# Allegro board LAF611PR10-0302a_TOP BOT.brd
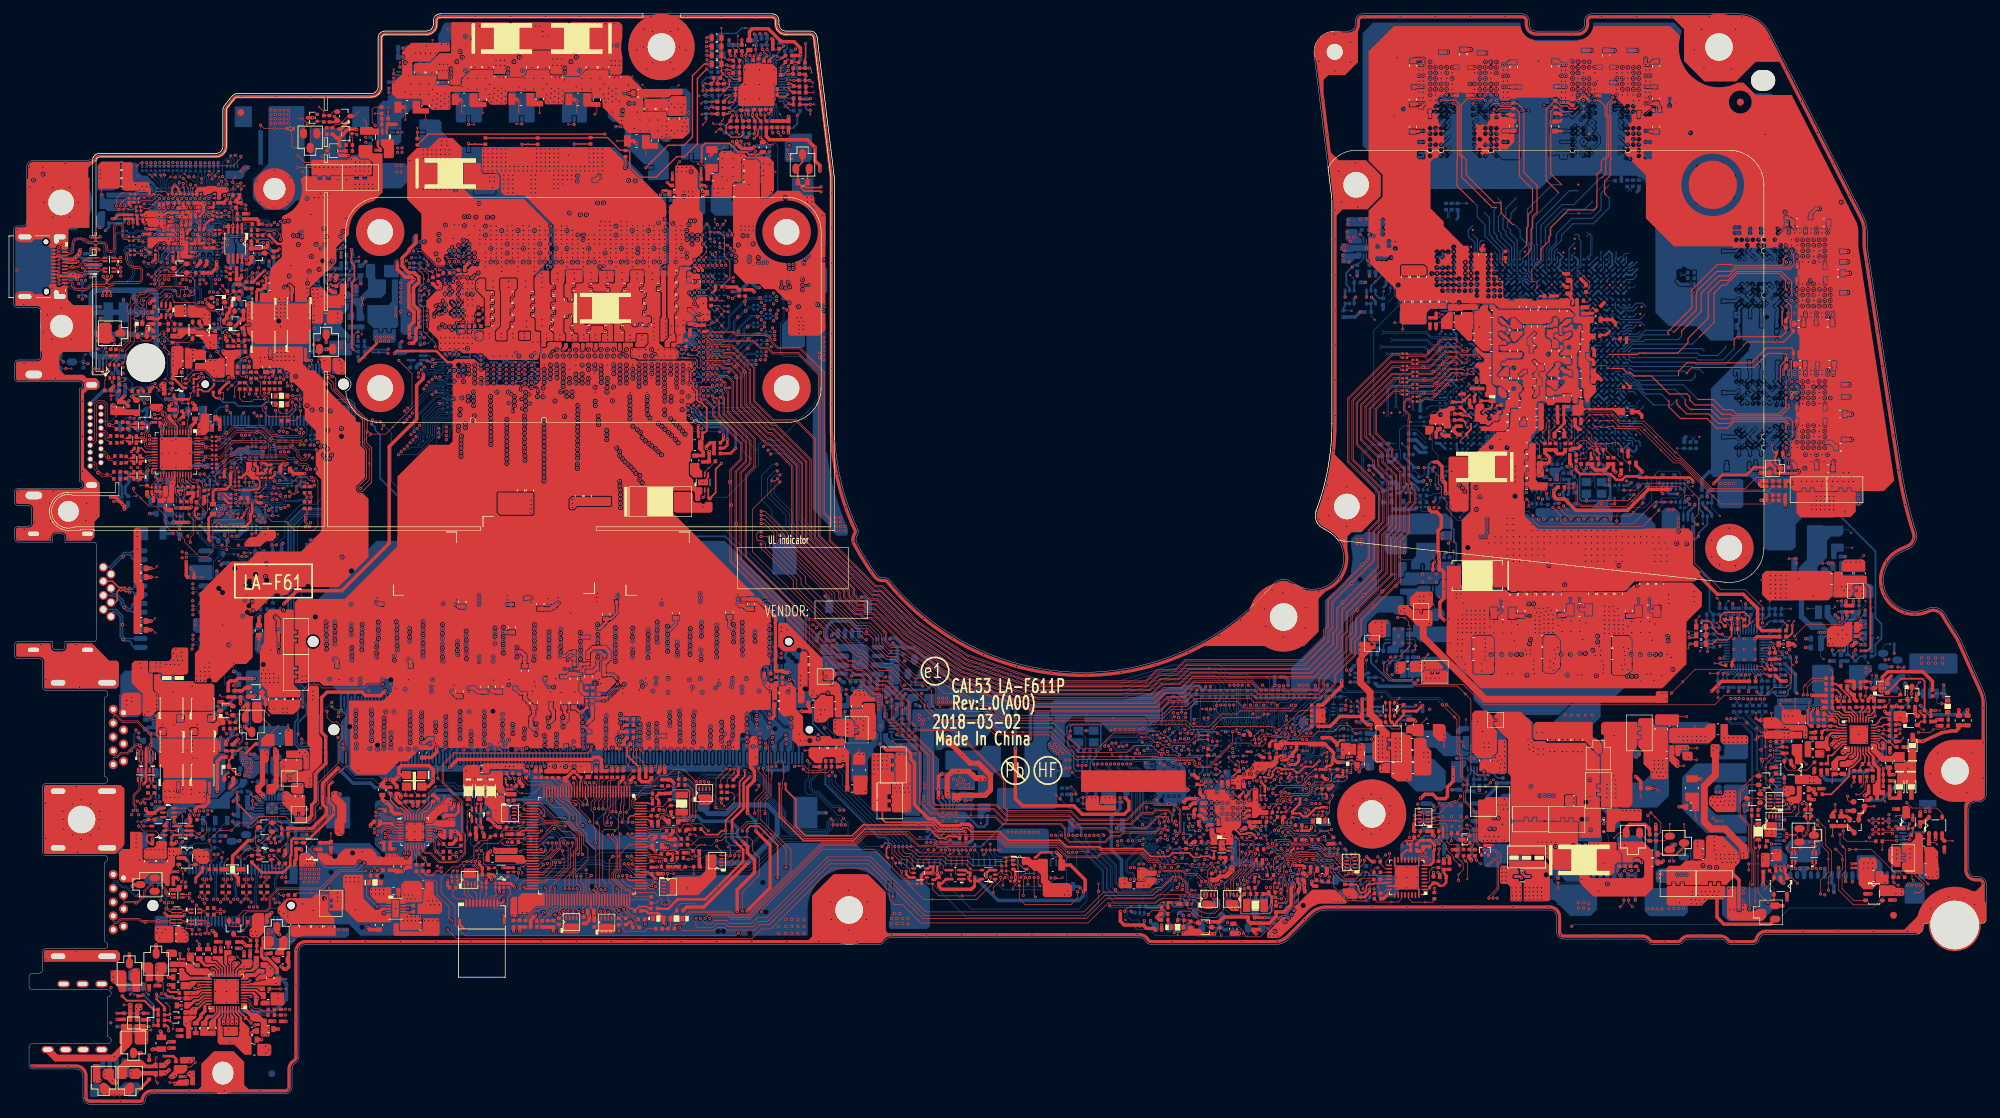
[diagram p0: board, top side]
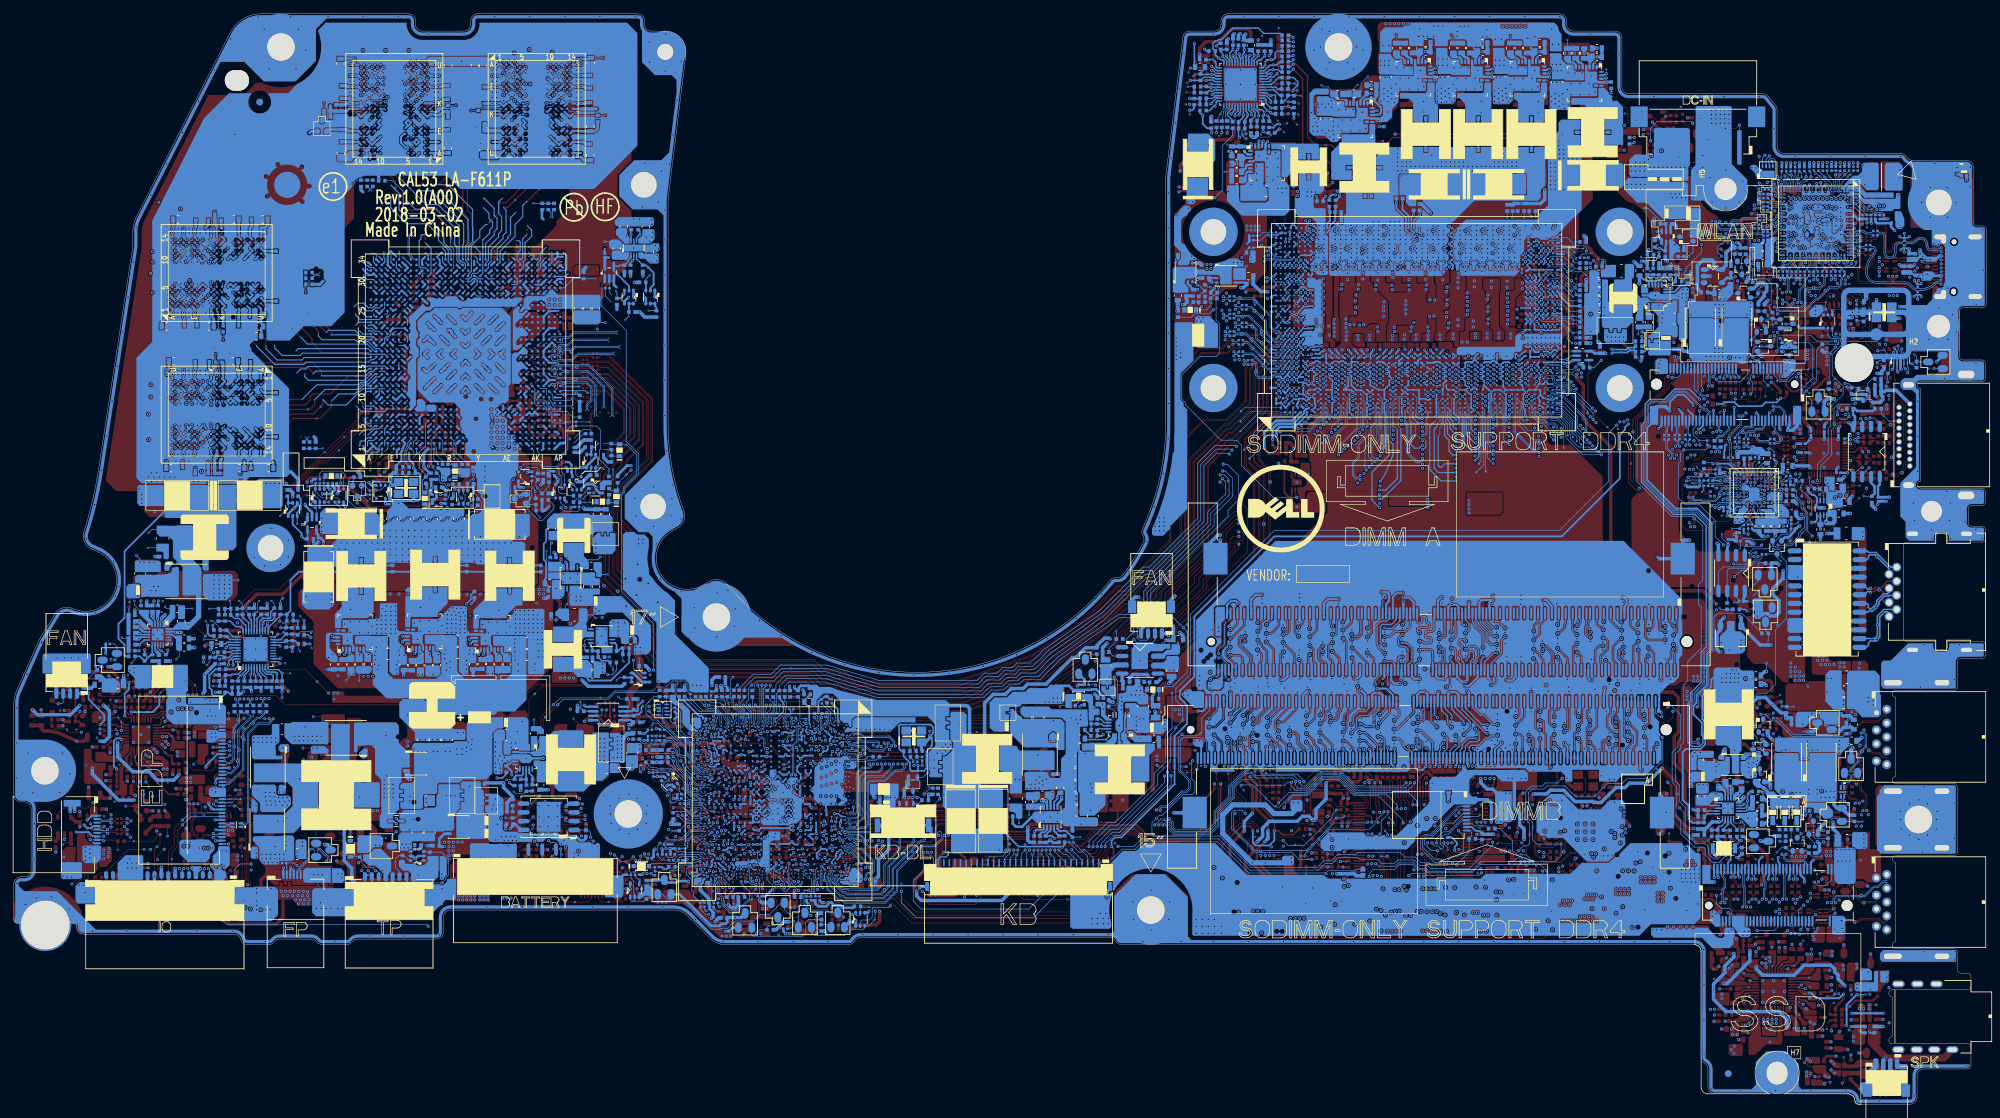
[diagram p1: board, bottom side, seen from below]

Outline 285.35 x 157.8 mm; copper layers: TOP, GND1, IN1, VCC, IN2, IN3, GND2, IN4, GND3, BOTTOM. Coordinates in mm from the lower left corner of the outline.

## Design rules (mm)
net group DDR4_RESET_20: nets DDR_DRAMRST# H_DRAMRST#
net group DDR_A_CLK0: nets DDR_A_CLK0 DDR_A_CLK#0
net group DDR_A_CLK1: nets DDR_A_CLK1 DDR_A_CLK#1
net group DDR_B_CLK0: nets DDR_B_CLK0 DDR_B_CLK#0
net group DDR_B_CLK1: nets DDR_B_CLK1 DDR_B_CLK#1
net group DIFFPAIR0: nets N26540304 N26540350
net group DIFFPAIR1: nets N26540312 N26540344
net group DIFFPAIR2: nets N26540318 N26540338
net group DIFFPAIR3: nets N26540324 N26540332
net group DIFFPAIR4: nets FB_A_CLK1 FB_A_CLK1#
net group DIFFPAIR5: nets FB_A_WCK3 FB_A_WCK#3
net group DIFFPAIR6: nets FB_A_WCK1 FB_A_WCK#1
net group DIFFPAIR7: nets FB_A_CLK0 FB_A_CLK0#
net group DIFFPAIR8: nets FB_B_CLK1 FB_B_CLK1#
net group DIFFPAIR9: nets FB_B_WCK2 FB_B_WCK#2
net group DIFFPAIR10: nets FB_B_WCK1 FB_B_WCK#1
net group DIFFPAIR11: nets FB_B_CLK0 FB_B_CLK0#
net group DIFFPAIR12: nets FB_A_WCK2 FB_A_WCK#2
net group DIFFPAIR13: nets FB_B_WCK3 FB_B_WCK#3
net group DIFFPAIR14: nets FB_B_WCK0 FB_B_WCK#0
net group DIFFPAIR15: nets FB_A_WCK0 FB_A_WCK#0
net group DIFFPAIR16: nets PCH_SMBCLK PCH_SMBDATA
net group DIFFPAIR17: nets CPU_DP1_N1_C CPU_DP1_P1_C
net group DIFFPAIR18: nets CPU_DP1_N0_C CPU_DP1_P0_C
net group DIFFPAIR19: nets CPU_DP1_N2_C CPU_DP1_P2_C
net group DIFFPAIR20: nets CPU_DP1_N3_C CPU_DP1_P3_C
net group DIFFPAIR21: nets PCIE_PTX_C_CRX_N23 PCIE_PTX_C_DRX_P23
net group DIFFPAIR22: nets TBT_A_SBU1 TBT_A_SBU2
net group PCIE_PRX_C_DTX_21: nets PCIE_PRX_C_DTX_N21 PCIE_PRX_C_DTX_P21
net group PCIE_PRX_C_DTX_22: nets PCIE_PRX_C_DTX_N22 PCIE_PRX_C_DTX_P22
net group PCIE_PRX_C_DTX_23: nets PCIE_PRX_C_DTX_N23 PCIE_PRX_C_DTX_P23
net group PCIE_PRX_C_DTX_24: nets PCIE_PRX_C_DTX_N24 PCIE_PRX_C_DTX_P24
net group PCIE_PRX_DTX_21: nets PCIE_PRX_DTX_N21 PCIE_PRX_DTX_P21
net group PCIE_PRX_DTX_22: nets PCIE_PRX_DTX_N22 PCIE_PRX_DTX_P22
net group PCIE_PRX_DTX_23: nets PCIE_PRX_DTX_N23 PCIE_PRX_DTX_P23
net group PCIE_PRX_DTX_24: nets PCIE_PRX_DTX_N24 PCIE_PRX_DTX_P24
net group PCIE_PTX_C_DRX_21: nets PCIE_PTX_C_DRX_N21 PCIE_PTX_C_DRX_P21
net group PCIE_PTX_C_DRX_22: nets PCIE_PTX_C_DRX_N22 PCIE_PTX_C_DRX_P22
net group PCIE_PTX_C_DRX_24: nets PCIE_PTX_C_DRX_N24 PCIE_PTX_C_DRX_P24
net group PCIE_PTX_DRX_21: nets PCIE_PTX_DRX_N21 PCIE_PTX_DRX_P21
net group PCIE_PTX_DRX_22: nets PCIE_PTX_DRX_N22 PCIE_PTX_DRX_P22
net group PCIE_PTX_DRX_23: nets PCIE_PTX_DRX_N23 PCIE_PTX_DRX_P23
net group PCIE_PTX_DRX_24: nets PCIE_PTX_DRX_N24 PCIE_PTX_DRX_P24
net group PCIE_RCOMP: nets PCIE_RCOMPN PCIE_RCOMPP
net group TBTA_DIG_AUD_: nets TBTA_DIG_AUD_N TBTA_DIG_AUD_P
net group THERMAL_10: nets NCT7718_DXN NCT7718_DXP
net group USB20_5_R: nets USB20_N5_R USB20_P5_R
net group USB20_8_R: nets USB20_N8_R USB20_P8_R
net group USB20_11: nets USB20_N11 USB20_P11
net group AR_TO_TYPEC_15: nets TBT_A_AUX_N TBT_A_AUX_N_C TBT_A_AUX_P TBT_A_AUX_P_C
net group ASYN_SIGNALS_12: nets ALL_SYS_PWRGD CATERR# DGPU_HOLD_RST# DGPU_PEX_RST# DGPU_PEX_RST#_R H_CPUPWRGD H_PLTRST_CPU# H_PROCHOT# H_PROCHOT#_R H_THERMTRIP# H_THERMTRIP#_C H_THERMTRIP#_R H_VCCST_PWRGD N17462343 PCH_PLTRST# PLTRST# PROCHOT RUNPWROK TBT_RST#_R VCCST_PWRGD_CPU XDP_BPM#0 XDP_BPM#1 XDP_BPM#2 XDP_BPM#3
net group ASYN_SIGNALS_OTHER_15/12: nets CPU_TRIGOUT CPU_TRIGOUT_R H_PM_DOWN H_PM_DOWN_R H_PM_SYNC_PCH H_PM_SYNC_R PCH_TRIGOUT PCH_TRIGOUT_R
net group ASYN_SIGNALS_PECI_18/12: nets H_PECI PECI_EC PECI_EC_R
net group ASYN_SIGNALS_SVID_15/12: nets VR_SVID_ALERT# VR_SVID_ALERT#_R VR_SVID_CLK VR_SVID_DATA
net group AUDIO_12: nets CBN CBP CPVEE
net group AUDIO_ANALOG_PORT_10: nets +MIC2-VREFO AUD_HP1_JACK_L AUD_HP1_JACK_L1 AUD_HP1_JACK_R AUD_HP1_JACK_R1 HPOUT_L HPOUT_R LINE1-L_C LINE1-L_R LINE1_L LINE1_R
net group AUDIO_LDO: nets LDO1_CAP LDO2_CAP LDO3_CAP
net group AUDIO_SPEAKER_10: nets AUD_SPK_L+ AUD_SPK_L+_C AUD_SPK_L- AUD_SPK_L-_C AUD_SPK_R+ AUD_SPK_R+_C AUD_SPK_R- AUD_SPK_R-_C RING2 RING2_R SLEEVE SLEEVE_R
net group CLK_DIFF: nets CLK_PCIE_N0 CLK_PCIE_N7 CLK_PCIE_N9 CLK_PCIE_N14 CLK_PCIE_N15 CLK_PCIE_P0 CLK_PCIE_P7 CLK_PCIE_P9 CLK_PCIE_P14 CLK_PCIE_P15 CPU_24MHZ_N CPU_24MHZ_P PCH_CPU_BCLK_N PCH_CPU_BCLK_P PCH_CPU_PCIBCLK_N PCH_CPU_PCIBCLK_P PCH_XDP_CLK_N PCH_XDP_CLK_P
net group CLK_SRCCLKREQ: nets CLKREQ_PCIE#0 CLKREQ_PCIE#0_R CLKREQ_PCIE#7 CLKREQ_PCIE#9 CLKREQ_PCIE#14 CLKREQ_PCIE#14_R CLKREQ_PCIE#15 CLKREQ_PCIE#15_R PEX_CLKREQ#
net group CLKIN_XTAL: nets CLKREQ_CNV# REFCLK_CNV REFCLK_CNV_H
net group CNVI: nets CLK_CNV_PRX_DTX_N CLK_CNV_PRX_DTX_P CLK_CNV_PRX_R_DTX_N CLK_CNV_PRX_R_DTX_P CLK_CNV_PTX_DRX_N CLK_CNV_PTX_DRX_P CLK_CNV_PTX_R_DRX_N CLK_CNV_PTX_R_DRX_P CNV_PRX_DTX_N0 CNV_PRX_DTX_N1 CNV_PRX_DTX_P0 CNV_PRX_DTX_P1 CNV_PRX_R_DTX_N0 CNV_PRX_R_DTX_N1 CNV_PRX_R_DTX_P0 CNV_PRX_R_DTX_P1 CNV_PTX_DRX_N0 CNV_PTX_DRX_N1 CNV_PTX_DRX_P0 CNV_PTX_DRX_P1 CNV_PTX_R_DRX_N0 CNV_PTX_R_DRX_N1 CNV_PTX_R_DRX_P0 CNV_PTX_R_DRX_P1
net group CNVI_BRI_RGI: nets CNV_BRI_PRX_DTX CNV_BRI_PTX_DRX CNV_RGI_PRX_DTX CNV_RGI_PTX_DRX
net group CPU_PEG_RCOMP_15: nets PEG_RCOMP
net group CRITICAL_ RESET_MANAGEMENT_15: nets 1.2V_VDDQ_EN AC_PRESENT CNV_RF_RESET# HW_ACAV_IN LAN_WAKE# LANWAKE# ME_SUS_PWR_ACK PCH_BATLOW# PCH_DPWROK PCH_PCIE_WAKE# PCH_PWROK PCH_RSMRST# PCH_RSMRST#_R PCIE_WAKE# RESET_N RTM_RST# SIO_PWRBTN# SIO_SLP_S0# SIO_SLP_S0#_PCH SIO_SLP_S3# SIO_SLP_S3#_AR SIO_SLP_S3#_PCH SIO_SLP_S4# SIO_SLP_S4#_PCH SYS_PWROK SYS_RESET# TBT_PCIE_WAKE_N TBT_RESET_N TBT_RESET_N_EC# TBTA_MRESET USB_EN# VCCIO_EN VR_ON
net group DDR4_COMP: nets SM_RCOMP0 SM_RCOMP1 SM_RCOMP2
net group DDRA_CMD: nets DDR_A_ACT# DDR_A_ALERT# DDR_A_BA0 DDR_A_BA1 DDR_A_BG0 DDR_A_BG1 DDR_A_MA0 DDR_A_MA1 DDR_A_MA2 DDR_A_MA3 DDR_A_MA4 DDR_A_MA5 DDR_A_MA6 DDR_A_MA7 DDR_A_MA8 DDR_A_MA9 DDR_A_MA10 DDR_A_MA11 DDR_A_MA12 DDR_A_MA13 DDR_A_MA14_WE# DDR_A_MA15_CAS# DDR_A_MA16_RAS# DDR_A_PAR
net group DDRA_CTRL: nets DDR_A_CKE0 DDR_A_CKE1 DDR_A_CS#0 DDR_A_CS#1 DDR_A_ODT0 DDR_A_ODT1
net group DDRA_D0: nets DDR_A_D0 DDR_A_D1 DDR_A_D2 DDR_A_D3 DDR_A_D4 DDR_A_D5 DDR_A_D6 DDR_A_D7
net group DDRA_D1: nets DDR_A_D8 DDR_A_D9 DDR_A_D10 DDR_A_D11 DDR_A_D12 DDR_A_D13 DDR_A_D14 DDR_A_D15
net group DDRA_D2: nets DDR_A_D16 DDR_A_D17 DDR_A_D18 DDR_A_D19 DDR_A_D20 DDR_A_D21 DDR_A_D22 DDR_A_D23
net group DDRA_D3: nets DDR_A_D24 DDR_A_D25 DDR_A_D26 DDR_A_D27 DDR_A_D28 DDR_A_D29 DDR_A_D30 DDR_A_D31
net group DDRA_D4: nets DDR_A_D32 DDR_A_D33 DDR_A_D34 DDR_A_D35 DDR_A_D36 DDR_A_D37 DDR_A_D38 DDR_A_D39
net group DDRA_D5: nets DDR_A_D40 DDR_A_D41 DDR_A_D42 DDR_A_D43 DDR_A_D44 DDR_A_D45 DDR_A_D46 DDR_A_D47
net group DDRA_D6: nets DDR_A_D48 DDR_A_D49 DDR_A_D50 DDR_A_D51 DDR_A_D52 DDR_A_D53 DDR_A_D54 DDR_A_D55
net group DDRA_D7: nets DDR_A_D56 DDR_A_D57 DDR_A_D58 DDR_A_D59 DDR_A_D60 DDR_A_D61 DDR_A_D62 DDR_A_D63
net group DDRA_DQS_25: nets DDR_A_DQS0 DDR_A_DQS1 DDR_A_DQS2 DDR_A_DQS3 DDR_A_DQS4 DDR_A_DQS5 DDR_A_DQS6 DDR_A_DQS7 DDR_A_DQS#0 DDR_A_DQS#1 DDR_A_DQS#2 DDR_A_DQS#3 DDR_A_DQS#4 DDR_A_DQS#5 DDR_A_DQS#6 DDR_A_DQS#7
net group DDRB_CMD: nets DDR_B_ACT# DDR_B_ALERT# DDR_B_BA0 DDR_B_BA1 DDR_B_BG0 DDR_B_BG1 DDR_B_MA0 DDR_B_MA1 DDR_B_MA2 DDR_B_MA3 DDR_B_MA4 DDR_B_MA5 DDR_B_MA6 DDR_B_MA7 DDR_B_MA8 DDR_B_MA9 DDR_B_MA10 DDR_B_MA11 DDR_B_MA12 DDR_B_MA13 DDR_B_MA14_WE# DDR_B_MA15_CAS# DDR_B_MA16_RAS# DDR_B_PAR
net group DDRB_CTRL: nets DDR_B_CKE0 DDR_B_CKE1 DDR_B_CS#0 DDR_B_CS#1 DDR_B_ODT0 DDR_B_ODT1
net group DDRB_D0: nets DDR_B_D0 DDR_B_D1 DDR_B_D2 DDR_B_D3 DDR_B_D4 DDR_B_D5 DDR_B_D6 DDR_B_D7
net group DDRB_D1: nets DDR_B_D8 DDR_B_D9 DDR_B_D10 DDR_B_D11 DDR_B_D12 DDR_B_D13 DDR_B_D14 DDR_B_D15
net group DDRB_D2: nets DDR_B_D16 DDR_B_D17 DDR_B_D18 DDR_B_D19 DDR_B_D20 DDR_B_D21 DDR_B_D22 DDR_B_D23
net group DDRB_D3: nets DDR_B_D24 DDR_B_D25 DDR_B_D26 DDR_B_D27 DDR_B_D28 DDR_B_D29 DDR_B_D30 DDR_B_D31
net group DDRB_D4: nets DDR_B_D32 DDR_B_D33 DDR_B_D34 DDR_B_D35 DDR_B_D36 DDR_B_D37 DDR_B_D38 DDR_B_D39
net group DDRB_D5: nets DDR_B_D40 DDR_B_D41 DDR_B_D42 DDR_B_D43 DDR_B_D44 DDR_B_D45 DDR_B_D46 DDR_B_D47
net group DDRB_D6: nets DDR_B_D48 DDR_B_D49 DDR_B_D50 DDR_B_D51 DDR_B_D52 DDR_B_D53 DDR_B_D54 DDR_B_D55
net group DDRB_D7: nets DDR_B_D56 DDR_B_D57 DDR_B_D58 DDR_B_D59 DDR_B_D60 DDR_B_D61 DDR_B_D62 DDR_B_D63
net group DDRB_DQS_25: nets DDR_B_DQS0 DDR_B_DQS1 DDR_B_DQS2 DDR_B_DQS3 DDR_B_DQS4 DDR_B_DQS5 DDR_B_DQS6 DDR_B_DQS7 DDR_B_DQS#0 DDR_B_DQS#1 DDR_B_DQS#2 DDR_B_DQS#3 DDR_B_DQS#4 DDR_B_DQS#5 DDR_B_DQS#6 DDR_B_DQS#7
net group DMI: nets DMI_CRX_PTX_N0 DMI_CRX_PTX_N1 DMI_CRX_PTX_N2 DMI_CRX_PTX_N3 DMI_CRX_PTX_P0 DMI_CRX_PTX_P1 DMI_CRX_PTX_P2 DMI_CRX_PTX_P3 DMI_CTX_PRX_N0 DMI_CTX_PRX_N1 DMI_CTX_PRX_N2 DMI_CTX_PRX_N3 DMI_CTX_PRX_P0 DMI_CTX_PRX_P1 DMI_CTX_PRX_P2 DMI_CTX_PRX_P3
net group DP_MAIN_15: nets CPU_DP1_AUXN CPU_DP1_AUXN_C CPU_DP1_AUXP CPU_DP1_AUXP_C CPU_DP1_N0 CPU_DP1_N1 CPU_DP1_N2 CPU_DP1_N3 CPU_DP1_P0 CPU_DP1_P1 CPU_DP1_P2 CPU_DP1_P3
net group EDP: nets EDP_AUXN EDP_AUXN_C EDP_AUXP EDP_AUXP_C EDP_TXN0 EDP_TXN0_C EDP_TXN1 EDP_TXN1_C EDP_TXP0 EDP_TXP0_C EDP_TXP1 EDP_TXP1_C
net group EDP_COMP_20: nets DP_RCOMP
net group ESPI_15: nets ESPI_CLK ESPI_CLK_R ESPI_CS# ESPI_IO0 ESPI_IO0_R ESPI_IO1 ESPI_IO1_R ESPI_IO2 ESPI_IO2_R ESPI_IO3 ESPI_IO3_R
net group HDA_15: nets CPU_DISPA_BCLK CPU_DISPA_BCLK_R CPU_DISPA_SDI CPU_DISPA_SDI_C CPU_DISPA_SDO CPU_DISPA_SDO_R DMIC_CLK DMIC_CLK_EDP DMIC_DATA DMIC_DATA_EDP HDA_CODEC_SDIN0 PCH_AZ_BITCLK PCH_AZ_CODEC_BITCLK PCH_AZ_CODEC_SDIN0 PCH_AZ_CODEC_SDOUT PCH_AZ_CODEC_SYNC PCH_AZ_SDOUT PCH_AZ_SYNC
net group HDMI: nets HDMI_CLKN HDMI_CLKP HDMI_L_CLKN HDMI_L_CLKP HDMI_L_TX_N0 HDMI_L_TX_N1 HDMI_L_TX_N2 HDMI_L_TX_P0 HDMI_L_TX_P1 HDMI_L_TX_P2 HDMI_TX_N0 HDMI_TX_N1 HDMI_TX_N2 HDMI_TX_P0 HDMI_TX_P1 HDMI_TX_P2 IFPC_CLK_CN IFPC_CLK_CP IFPC_CLK_N IFPC_CLK_P IFPC_TX0_CN IFPC_TX0_CP IFPC_TX0_N IFPC_TX0_P IFPC_TX1_CN IFPC_TX1_CP IFPC_TX1_N IFPC_TX1_P IFPC_TX2_CN IFPC_TX2_CP IFPC_TX2_N IFPC_TX2_P
net group HDMI_DDC_15: nets HDMI_CTRL_CLK HDMI_CTRL_DAT IFPC_I2C_8409_CLK IFPC_I2C_8409_DAT IFPC_I2C_CLK IFPC_I2C_CLK_R IFPC_I2C_DAT IFPC_I2C_DAT_R
net group I2C_15: nets CLK_TP_SIO DAT_TP_SIO I2C_SCL_TP I2C_SDA_TP
net group LAN_30: nets LAN_MDIN0 LAN_MDIN1 LAN_MDIN2 LAN_MDIN3 LAN_MDIP0 LAN_MDIP1 LAN_MDIP2 LAN_MDIP3 RJ45_MDIN0 RJ45_MDIN1 RJ45_MDIN2 RJ45_MDIN3 RJ45_MDIP0 RJ45_MDIP1 RJ45_MDIP2 RJ45_MDIP3
net group NVME_PCIE_12: nets PCIE_PRX_DTX_N9 PCIE_PRX_DTX_N10 PCIE_PRX_DTX_N11 PCIE_PRX_DTX_N12 PCIE_PRX_DTX_P9 PCIE_PRX_DTX_P10 PCIE_PRX_DTX_P11 PCIE_PRX_DTX_P12 PCIE_PTX_C_DRX_N9 PCIE_PTX_C_DRX_N10 PCIE_PTX_C_DRX_N11 PCIE_PTX_C_DRX_N12 PCIE_PTX_C_DRX_P9 PCIE_PTX_C_DRX_P10 PCIE_PTX_C_DRX_P11 PCIE_PTX_C_DRX_P12 PCIE_PTX_DRX_N9 PCIE_PTX_DRX_N10 PCIE_PTX_DRX_N11 PCIE_PTX_DRX_N12 PCIE_PTX_DRX_P9 PCIE_PTX_DRX_P10 PCIE_PTX_DRX_P11 PCIE_PTX_DRX_P12
net group PCIE_12: nets PCIE_PRX_C_DTX_N14 PCIE_PRX_C_DTX_P14 PCIE_PRX_DTX_N14 PCIE_PRX_DTX_N15 PCIE_PRX_DTX_P14 PCIE_PRX_DTX_P15 PCIE_PTX_C_DRX_N14 PCIE_PTX_C_DRX_N15 PCIE_PTX_C_DRX_P14 PCIE_PTX_C_DRX_P15 PCIE_PTX_DRX_N14 PCIE_PTX_DRX_N15 PCIE_PTX_DRX_P14 PCIE_PTX_DRX_P15
net group PEG: nets PEG_CRX_C_GTX_N0 PEG_CRX_C_GTX_N1 PEG_CRX_C_GTX_N2 PEG_CRX_C_GTX_N3 PEG_CRX_C_GTX_N4 PEG_CRX_C_GTX_N5 PEG_CRX_C_GTX_N6 PEG_CRX_C_GTX_N7 PEG_CRX_C_GTX_P0 PEG_CRX_C_GTX_P1 PEG_CRX_C_GTX_P2 PEG_CRX_C_GTX_P3 PEG_CRX_C_GTX_P4 PEG_CRX_C_GTX_P5 PEG_CRX_C_GTX_P6 PEG_CRX_C_GTX_P7 PEG_CRX_GTX_N0 PEG_CRX_GTX_N1 PEG_CRX_GTX_N2 PEG_CRX_GTX_N3 PEG_CRX_GTX_N4 PEG_CRX_GTX_N5 PEG_CRX_GTX_N6 PEG_CRX_GTX_N7 PEG_CRX_GTX_P0 PEG_CRX_GTX_P1 PEG_CRX_GTX_P2 PEG_CRX_GTX_P3 PEG_CRX_GTX_P4 PEG_CRX_GTX_P5 PEG_CRX_GTX_P6 PEG_CRX_GTX_P7 PEG_CTX_GRX_N0 PEG_CTX_GRX_N1 PEG_CTX_GRX_N2 PEG_CTX_GRX_N3 PEG_CTX_GRX_N4 PEG_CTX_GRX_N5 PEG_CTX_GRX_N6 PEG_CTX_GRX_N7 PEG_CTX_GRX_P0 PEG_CTX_GRX_P1 PEG_CTX_GRX_P2 PEG_CTX_GRX_P3 PEG_CTX_GRX_P4 PEG_CTX_GRX_P5 PEG_CTX_GRX_P6 PEG_CTX_GRX_P7
net group PEG_1: nets PEG_CTX_C_GRX_N0 PEG_CTX_C_GRX_N1 PEG_CTX_C_GRX_N2 PEG_CTX_C_GRX_N3 PEG_CTX_C_GRX_N4 PEG_CTX_C_GRX_N5 PEG_CTX_C_GRX_N6 PEG_CTX_C_GRX_N7 PEG_CTX_C_GRX_P0 PEG_CTX_C_GRX_P1 PEG_CTX_C_GRX_P2 PEG_CTX_C_GRX_P3 PEG_CTX_C_GRX_P4 PEG_CTX_C_GRX_P5 PEG_CTX_C_GRX_P6 PEG_CTX_C_GRX_P7
net group RTC_15: nets MEC_XTAL1 MEC_XTAL1_R MEC_XTAL2 PCH_RTCRST# PCH_RTCX1 PCH_RTCX2 PCH_SRTCRST# SUSCLK SUSCLK_EC SUSCLK_WLAN
net group SATA_HDD_12: nets SATA3_PRX_C_DTX_N0 SATA3_PRX_C_DTX_P0 SATA3_PRX_DTX_N0 SATA3_PRX_DTX_P0 SATA3_PTX_C_DRX_N0 SATA3_PTX_C_DRX_P0 SATA3_PTX_DRX_N0 SATA3_PTX_DRX_P0
net group SENSE_25: nets FBVDDQ_SENSE N26985058 N26985064 USB2_VBUSSENSE VCC_SA_SENSE VCC_SENSE VCCGT_SENSE VCCIO_SENSE VSS_SA_SENSE VSS_SENSE VSSGT_SENSE VSSIO_SENSE
net group SMBUS_15: nets CLK_SMB DAT_SMB GPU_THM_SMBCLK GPU_THM_SMBDAT PBAT_CHG_SMBCLK PBAT_CHG_SMBDAT PD_I2C_SCL_R PD_I2C_SDA_R SMBCLK SMBDATA SML0_SMBCLK SML0_SMBDATA THM_SML1_CLK THM_SML1_DATA TYPEC_SMBCLK TYPEC_SMBDA VGA_SMB_CK2 VGA_SMB_DA2
net group SPI_15: nets PCH_SPI_CLK PCH_SPI_CLK_R PCH_SPI_CLK_TPM PCH_SPI_CS2# PCH_SPI_CS# PCH_SPI_HOLD# PCH_SPI_HOLD#_R PCH_SPI_SI PCH_SPI_SI_R PCH_SPI_SI_TPM PCH_SPI_SO PCH_SPI_SO_R PCH_SPI_SO_TPM PCH_SPI_WP# PCH_SPI_WP#_R
net group TBT: nets TBT_A_TRX_DTX_N0 TBT_A_TRX_DTX_N0_R TBT_A_TRX_DTX_N1 TBT_A_TRX_DTX_N1_R TBT_A_TRX_DTX_P0 TBT_A_TRX_DTX_P0_R TBT_A_TRX_DTX_P1 TBT_A_TRX_DTX_P1_R TBT_A_TTX_C_DRX_N0 TBT_A_TTX_C_DRX_N1 TBT_A_TTX_C_DRX_P0 TBT_A_TTX_C_DRX_P1 TBT_A_TTX_DRX_N0 TBT_A_TTX_DRX_N1 TBT_A_TTX_DRX_P0 TBT_A_TTX_DRX_P1
net group USB2.0_RBIAS_15: nets USB2_COMP
net group USB2.0_TBT_12: nets TBT_A_USB20_L_NB TBT_A_USB20_L_NT TBT_A_USB20_L_PB TBT_A_USB20_L_PT TBT_A_USB20_N TBT_A_USB20_NB TBT_A_USB20_NT TBT_A_USB20_P TBT_A_USB20_PB TBT_A_USB20_PT
net group USB_2.0_12: nets USB20_N1 USB20_N1_R USB20_N2 USB20_N2_R USB20_N3 USB20_N3_R USB20_N4 USB20_N4_R USB20_N5 USB20_N6 USB20_N6_R USB20_N7 USB20_N8 USB20_N9 USB20_N14 USB20_P1 USB20_P1_R USB20_P2 USB20_P2_R USB20_P3 USB20_P3_R USB20_P4 USB20_P4_R USB20_P5 USB20_P6 USB20_P6_R USB20_P7 USB20_P8 USB20_P9 USB20_P14
net group USB_3.0_12: nets USB3_PRX_DTX_N1 USB3_PRX_DTX_N3 USB3_PRX_DTX_P1 USB3_PRX_DTX_P3 USB3_PRX_L_DTX_N1 USB3_PRX_L_DTX_N3 USB3_PRX_L_DTX_P1 USB3_PRX_L_DTX_P3 USB3_PTX_C_DRX_N1 USB3_PTX_C_DRX_N3 USB3_PTX_C_DRX_P1 USB3_PTX_C_DRX_P3 USB3_PTX_DRX_N1 USB3_PTX_DRX_N3 USB3_PTX_DRX_P1 USB3_PTX_DRX_P3 USB3_PTX_L_DRX_N1 USB3_PTX_L_DRX_N3 USB3_PTX_L_DRX_P1 USB3_PTX_L_DRX_P3
net group VRAM_FB_A_0_12: nets FB_A_D0 FB_A_D1 FB_A_D2 FB_A_D3 FB_A_D4 FB_A_D5 FB_A_D6 FB_A_D7
net group VRAM_FB_A_1_12: nets FB_A_D8 FB_A_D9 FB_A_D10 FB_A_D11 FB_A_D12 FB_A_D13 FB_A_D14 FB_A_D15
net group VRAM_FB_A_2_12: nets FB_A_D16 FB_A_D17 FB_A_D18 FB_A_D19 FB_A_D20 FB_A_D21 FB_A_D22 FB_A_D23
net group VRAM_FB_A_3_12: nets FB_A_D24 FB_A_D25 FB_A_D26 FB_A_D27 FB_A_D28 FB_A_D29 FB_A_D30 FB_A_D31
net group VRAM_FB_A_4_12: nets FB_A_D32 FB_A_D33 FB_A_D34 FB_A_D35 FB_A_D36 FB_A_D37 FB_A_D38 FB_A_D39
net group VRAM_FB_A_5_12: nets FB_A_D40 FB_A_D41 FB_A_D42 FB_A_D43 FB_A_D44 FB_A_D45 FB_A_D46 FB_A_D47
net group VRAM_FB_A_6_12: nets FB_A_D48 FB_A_D49 FB_A_D50 FB_A_D51 FB_A_D52 FB_A_D53 FB_A_D54 FB_A_D55
net group VRAM_FB_A_7_12: nets FB_A_D57 FB_A_D58 FB_A_D59 FB_A_D60 FB_A_D61 FB_A_D62 FB_A_D63
net group VRAM_FB_A_CMD_19/12: nets FB_A_CMD0 FB_A_CMD1 FB_A_CMD2 FB_A_CMD3 FB_A_CMD4 FB_A_CMD5 FB_A_CMD6 FB_A_CMD7 FB_A_CMD8 FB_A_CMD9 FB_A_CMD10 FB_A_CMD11 FB_A_CMD12 FB_A_CMD13 FB_A_CMD14 FB_A_CMD15 FB_A_CMD16 FB_A_CMD17 FB_A_CMD18 FB_A_CMD19 FB_A_CMD20 FB_A_CMD21 FB_A_CMD22 FB_A_CMD23 FB_A_CMD24 FB_A_CMD25 FB_A_CMD26 FB_A_CMD27 FB_A_CMD28 FB_A_CMD29 FB_A_CMD30 FB_A_CMD31
net group VRAM_FB_A_DBI_12: nets FB_A_DBI0 FB_A_DBI1 FB_A_DBI2 FB_A_DBI3 FB_A_DBI4 FB_A_DBI5 FB_A_DBI6 FB_A_DBI7
net group VRAM_FB_A_EDC_12: nets FB_A_EDC0 FB_A_EDC1 FB_A_EDC2 FB_A_EDC3 FB_A_EDC4 FB_A_EDC5 FB_A_EDC6 FB_A_EDC7
net group VRAM_FB_B_0_12: nets FB_B_D0 FB_B_D1 FB_B_D2 FB_B_D3 FB_B_D4 FB_B_D5 FB_B_D6 FB_B_D7
net group VRAM_FB_B_1_12: nets FB_B_D8 FB_B_D9 FB_B_D10 FB_B_D11 FB_B_D12 FB_B_D13 FB_B_D14 FB_B_D15
net group VRAM_FB_B_2_12: nets FB_B_D16 FB_B_D17 FB_B_D18 FB_B_D19 FB_B_D20 FB_B_D21 FB_B_D22 FB_B_D23
net group VRAM_FB_B_3_12: nets FB_B_D24 FB_B_D25 FB_B_D26 FB_B_D27 FB_B_D28 FB_B_D29 FB_B_D30 FB_B_D31
net group VRAM_FB_B_4_12: nets FB_B_D32 FB_B_D33 FB_B_D34 FB_B_D35 FB_B_D36 FB_B_D37 FB_B_D38 FB_B_D39
net group VRAM_FB_B_5_12: nets FB_B_D40 FB_B_D41 FB_B_D42 FB_B_D43 FB_B_D44 FB_B_D45 FB_B_D46 FB_B_D47
net group VRAM_FB_B_6_12: nets FB_B_D48 FB_B_D49 FB_B_D50 FB_B_D51 FB_B_D52 FB_B_D53 FB_B_D54 FB_B_D55
net group VRAM_FB_B_7_12: nets FB_B_D56 FB_B_D57 FB_B_D58 FB_B_D59 FB_B_D60 FB_B_D61 FB_B_D62 FB_B_D63
net group VRAM_FB_B_CMD_19/12: nets FB_B_CMD0 FB_B_CMD1 FB_B_CMD2 FB_B_CMD3 FB_B_CMD4 FB_B_CMD5 FB_B_CMD6 FB_B_CMD7 FB_B_CMD8 FB_B_CMD9 FB_B_CMD10 FB_B_CMD11 FB_B_CMD12 FB_B_CMD13 FB_B_CMD14 FB_B_CMD15 FB_B_CMD16 FB_B_CMD17 FB_B_CMD18 FB_B_CMD19 FB_B_CMD20 FB_B_CMD21 FB_B_CMD22 FB_B_CMD23 FB_B_CMD24 FB_B_CMD25 FB_B_CMD26 FB_B_CMD27 FB_B_CMD28 FB_B_CMD29 FB_B_CMD30 FB_B_CMD31
net group VRAM_FB_B_DBI_12: nets FB_B_DBI0 FB_B_DBI1 FB_B_DBI2 FB_B_DBI3 FB_B_DBI4 FB_B_DBI5 FB_B_DBI6 FB_B_DBI7
net group VRAM_FB_B_EDC_12: nets FB_B_EDC0 FB_B_EDC1 FB_B_EDC2 FB_B_EDC3 FB_B_EDC4 FB_B_EDC5 FB_B_EDC6 FB_B_EDC7
net group XDP_15: nets CFG0 CFG1 CFG2 CFG4 CFG5 CFG6 CFG7 CFG8 CFG9 CFG10 CFG11 CFG12 CFG13 CFG14 CFG15 CFG16 CFG17 CFG18 CFG19 CPU_XDP_TCK0 CPU_XDP_TDI CPU_XDP_TDO CPU_XDP_TMS CPU_XDP_TRST# HDD_DEVSLP HDD_DEVSLP_R PCH_JTAG_TCK1 SSD_DEVSLP TOUCH_SCREEN_PD# USB_OC0# USB_OC1# USB_OC2# USB_OC3# XDP_HOOK0 XDP_ITP_PMODE XDP_PRDY# XDP_PREQ# XDP_PRSENT_CPU XDP_PRSENT_PCH XDP_SPI_SI
net group XTAL24_15_20: nets LANXIN LANXIN_R LANXOUT LANXOUT_R TBT_XTAL_25_IN TBT_XTAL_25_IN_R TBT_XTAL_25_OUT TBT_XTAL_25_OUT_R XCLK_BIASREF XTAL24_IN XTAL24_IN_R XTAL24_OUT XTAL24_OUT_R
nets with their own width: min track width 0.254; nets N30700583 N30700625 N30700675 N30700682 N30700690 N30700699 N30700734 N30909781 N30909795
nets with their own width: min track width 0.508; nets 5VS_FAN1 5VS_FAN2 +3V_PCH_PRIM +3V_SPI +PWR_SRC +VBUS_DC_TRIP ADP_CHG AUD_AGND BA BA_PWR BATT+ BYPSRC EC_AGND GND N21741739 N29040119 N29056076 VDD_CHG
nets with their own width: min track width 2.032; nets USB30_VCCA

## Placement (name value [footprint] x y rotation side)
C1  0.47U_0402_6.3V6K  [C_0402]  182.14 26.97 0 bottom
C2  0.1U_0402_16V7K  [C_0402]  253.48 53.81 90 top
C3  1U_0402_10V6K  [C_0402]  254.43 53.81 90 top
C4  0.1U_0603_50V7K  [C_0603]  258.7 55.89 270 top
C5  1000P_0402_50V7K  [C_0402]  257.58 55.49 270 top
C6  0.1U_0402_16V7K  [C_0402]  251.6 57.71 270 bottom
C7  0.1U_0402_16V7K  [C_0402]  250.7 57.71 270 bottom
C8  0.1U_0402_16V7K  [C_0402]  249.77 57.71 270 bottom
C9  0.1U_0402_16V7K  [C_0402]  248.82 57.71 270 bottom
C10  0.1U_0402_16V7K  [C_0402]  252.5 57.71 270 bottom
C11  0.1U_0402_16V7K  [C_0402]  253.43 57.71 270 bottom
C12  10P_0402_50V8J  [C_0402]  255.38 53.81 90 top
C14  33P_0402_50V8J  [C_0402]  257.38 44.23 90 top
C15  4.7U_0603_6.3V6K  [C_0603]  258.3 45.59 0 top
C16  10P_0402_50V8J  [C_0402]  253.64 38.1 90 top
C17  1U_0402_6.3V6K  [C_0402]  261.15 46.58 270 top
C18  .1U_0402_16V7K  [C_0402]  236.7 39.03 270 top
C19  0.1U_0402_16V7K  [C_0402]  224.29 34.73 180 bottom
C21  0.1U_0402_16V7K  [C_0402]  195.73 55.27 180 bottom
C22  470P_0603_50V8J  [C_0603]  113.43 133.42 0 top
C23  2200P_0402_50V7K  [C_0402]  195.65 56.19 90 bottom
C26  10P_0402_50V8J  [C_0402]  232.23 34.44 90 top
C27  10P_0402_50V8J  [C_0402]  234.72 34.42 90 top
C30  22U_0805_10V6M  [C_0805]  120.17 57.66 270 bottom
C31  1U_0402_10V6K  [C_0402]  253.09 34.59 270 top
C32  0.1U_0402_16V7K  [C_0402]  67.25 114.35 270 top
C33  100P_0402_50V8J  [C_0402]  102.29 46.02 0 top
C34  .1U_0402_16V7K  [C_0402]  159.11 43.74 270 top
C37  0.1U_0402_16V7K  [C_0402]  238.93 32.49 0 bottom
C46  68P_0201_50V8J  [C_0201]  239.71 33.88 180 bottom
C47  68P_0201_50V8J  [C_0201]  256.81 55.3 270 top
C48  68P_0201_50V8J  [C_0201]  256.27 33.77 180 top
C49  68P_0201_50V8J  [C_0201]  256.64 44.14 90 top
C50  10P_0201_50V8J  [C_0201]  239.71 33.25 180 bottom
C51  68P_0201_50V8J  [C_0201]  157.46 43.65 270 top
C52  68P_0201_50V8J  [C_0201]  224.11 33.93 180 bottom
C53  68P_0201_50V8J  [C_0201]  56.1 25.93 180 top
C54  33P_0201_25V8F  [C_0201]  56.1 25.35 180 top
C55  68P_0201_50V8J  [C_0201]  58.87 29.46 0 top
C56  33P_0201_25V8F  [C_0201]  58.87 30.02 0 top
C59  1U_0402_6.3V6K  [C_0402]  193.83 32.37 270 bottom
C60  22P_0402_50V8J  [C_0402]  170.24 26.44 270 top
C61  0.1U_0402_25V6  [C_0402]  166.97 26.68 180 top
C148  22U_0805_10V6M  [C_0805]  271.17 60.91 180 bottom
C149  .1U_0402_16V7K  [C_0402]  153.95 43.99 180 bottom
C150  .1U_0402_16V7K  [C_0402]  158.22 43.74 270 top
C151  22U_0603_6.3V6M  [C_0603]  98.76 119.75 270 top
CA1  10U_0603_10V6M  [C_0603]  33.74 9.35 0 top
CA2  .1U_0402_16V7K  [C_0402]  29.79 10.21 0 top
CA3  10U_0603_10V6M  [C_0603]  33.74 10.62 0 top
CA4  .1U_0402_16V7K  [C_0402]  32.84 10.23 180 top
CA5  10U_0603_6.3V6M  [C_0603]  37.11 18.99 270 top
CA6  .1U_0402_16V7K  [C_0402]  35.99 17.52 90 top
CA7  .1U_0402_16V7K  [C_0402]  33.3 20.55 90 top
CA9  6.8P_0402_50V  [C_0402]  38.63 13.73 90 top
CA10  .1U_0402_16V7K  [C_0402]  26.57 19.24 90 top
CA11  10U_0603_10V6M  [C_0603]  25.5 19.63 90 top
CA12  10U_0603_6.3V6M  [C_0603]  28.73 10.3 90 top
CA13  10U_0603_6.3V6M  [C_0603]  38.23 20.84 0 top
CA14  .1U_0402_16V7K  [C_0402]  24.84 13.23 270 top
CA15  10U_0603_6.3V6M  [C_0603]  36.16 10.87 0 top
CA16  .1U_0402_16V7K  [C_0402]  36.14 12.01 0 top
CA20  10U_0603_6.3V6M  [C_0603]  23.08 18.36 0 top
CA21  10U_0603_6.3V6M  [C_0603]  27.52 10.3 90 top
CA22  10U_0603_6.3V6M  [C_0603]  37.5 15.7 180 top
CA23  2.2U_0603_6.3V6K  [C_0603]  24.47 17.09 180 top
CA24  2.2U_0603_6.3V6K  [C_0603]  26.31 11.7 270 top
CA25  1U_0603_16V7  [C_0603]  24.98 14.3 180 top
CA26  10U_0603_6.3V6M  [C_0603]  31.01 21.98 90 top
CA27  1000P_0402_50V7K  [C_0402]  24.14 3.08 90 top
CA28  1000P_0402_50V7K  [C_0402]  23.47 5.25 90 top
CA29  1000P_0402_50V7K  [C_0402]  19.58 5.46 90 top
CA30  1000P_0402_50V7K  [C_0402]  19.58 4.53 270 top
CA31  0.1U_0402_16V7K  [C_0402]  35.15 22.11 270 top
CA32  10U_0603_10V6M  [C_0603]  26.82 21.04 90 top
CA33  10U_0603_10V6M  [C_0603]  28.09 21.04 90 top
CA34  100P_0402_50V8J  [C_0402]  17.68 18.21 270 bottom
CA35  100P_0402_50V8J  [C_0402]  15.04 18.96 0 bottom
CA36  680P_0402_50V8J  [C_0402]  15.93 11.35 90 top
CA37  680P_0402_50V8J  [C_0402]  18.69 11.3 90 top
CA38  33P_0402_50V8J  [C_0402]  37.67 14.65 180 top
CA40  10P_0402_50V8J  [C_0402]  38.63 12.9 270 top
CA41  680P_0402_50V8J  [C_0402]  17.56 10.33 90 bottom
CA42  680P_0402_50V8J  [C_0402]  16.16 10.33 90 bottom
CA43  68P_0201_50V8J  [C_0201]  32.8 11 180 top
CA44  68P_0201_50V8J  [C_0201]  35.2 17.49 90 top
CA45  68P_0201_50V8J  [C_0201]  24.03 20.39 90 top
CA46  68P_0201_50V8J  [C_0201]  26.19 13.19 270 top
CA47  10P_0201_50V8J  [C_0201]  29.96 10.97 0 top
CA48  10P_0201_50V8J  [C_0201]  35.39 12.1 270 top
CA49  10P_0201_50V8J  [C_0201]  24.61 20.39 90 top
CA50  10P_0201_50V8J  [C_0201]  25.62 13.19 270 top
CA51  0.1U_0402_25V6  [C_0402]  29.23 23.5 90 top
CA52  0.1U_0402_25V6  [C_0402]  23.14 9.04 270 top
CA53  0.1U_0402_25V6  [C_0402]  24.31 9.86 0 top
CC1  0.22U_0201_6.3V6M  [C_0201]  106.21 107.04 0 bottom
CC2  0.22U_0201_6.3V6M  [C_0201]  106.21 107.68 0 bottom
CC3  0.22U_0201_6.3V6M  [C_0201]  107.54 108.92 0 bottom
CC4  0.22U_0201_6.3V6M  [C_0201]  107.54 108.29 0 bottom
CC5  0.22U_0201_6.3V6M  [C_0201]  107.54 109.93 0 bottom
CC6  0.22U_0201_6.3V6M  [C_0201]  107.54 110.57 0 bottom
CC7  0.22U_0201_6.3V6M  [C_0201]  108.83 111.83 0 bottom
CC8  0.22U_0201_6.3V6M  [C_0201]  108.83 111.2 0 bottom
CC9  0.22U_0201_6.3V6M  [C_0201]  107.05 112.47 0 bottom
CC10  0.22U_0201_6.3V6M  [C_0201]  107.05 113.1 0 bottom
CC11  0.22U_0201_6.3V6M  [C_0201]  108.83 114.37 0 bottom
CC12  0.22U_0201_6.3V6M  [C_0201]  108.83 113.74 0 bottom
CC13  0.22U_0201_6.3V6M  [C_0201]  107.05 115.01 0 bottom
CC14  0.22U_0201_6.3V6M  [C_0201]  107.05 115.64 0 bottom
CC15  0.22U_0201_6.3V6M  [C_0201]  108.83 116.28 0 bottom
CC16  0.22U_0201_6.3V6M  [C_0201]  108.83 116.91 0 bottom
CC17  10U_0402_6.3V6M  [C_0402]  81.41 109.88 0 top
CC18  10U_0402_6.3V6M  [C_0402]  89.28 109.88 0 top
CC19  10U_0402_6.3V6M  [C_0402]  85.12 109.88 180 top
CC20  10U_0402_6.3V6M  [C_0402]  84.17 88.53 270 top
CC21  10U_0402_6.3V6M  [C_0402]  86.74 109.88 0 top
CC22  10U_0402_6.3V6M  [C_0402]  78.97 109.85 0 top
CC23  10U_0402_6.3V6M  [C_0402]  77.5 109.91 180 top
CC24  10U_0402_6.3V6M  [C_0402]  70.39 89.17 270 top
CC25  10U_0402_6.3V6M  [C_0402]  71.34 89.17 270 top
CC26  10U_0402_6.3V6M  [C_0402]  72.3 89.17 270 top
CC27  10U_0402_6.3V6M  [C_0402]  86.07 88.53 270 top
CC28  10U_0402_6.3V6M  [C_0402]  85.12 88.53 270 top
CC29  22U_0603_6.3V6M  [C_0603]  73.37 89.53 270 top
CC30  22U_0603_6.3V6M  [C_0603]  74.64 89.53 270 top
CC31  22U_0603_6.3V6M  [C_0603]  81.76 88.71 270 top
CC32  22U_0603_6.3V6M  [C_0603]  83.03 88.71 270 top
CC33  10U_0402_6.3V6M  [C_0402]  97.83 112 180 top
CC34  10U_0402_6.3V6M  [C_0402]  97.78 112.92 90 top
CC35  10U_0402_6.3V6M  [C_0402]  97.78 114.96 90 top
CC36  1U_0201_6.3V6M  [C_0201]  99.63 96.54 180 top
CC37  1U_0201_6.3V6M  [C_0201]  99.63 97.18 180 top
CC38  1U_0201_6.3V6M  [C_0201]  97.61 119.14 270 top
CC39  1U_0201_6.3V6M  [C_0201]  97.77 120.33 90 top
CC40  1U_0201_6.3V6M  [C_0201]  99.07 120.62 0 top
CC41  0.5P_0402_50V8  [C_0402]  157.95 56.49 270 bottom
CC42  0.5P_0402_50V8  [C_0402]  159.77 56.51 270 bottom
CC43  0.5P_0402_50V8  [C_0402]  184.99 50.41 0 top
CC57  12P_0402_50V8J  [C_0402]  186.33 38.28 180 top
CC148  0.1U_0201_10V6K  [C_0201]  147.75 35.1 90 top
CC298  0.1U_0402_16V7K  [C_0402]  133.85 31.94 90 top
CC299  1000P_0402_50V7K  [C_0402]  35.33 37.16 270 bottom
CC300  .1U_0402_16V7K  [C_0402]  271.87 32.84 180 top
CC301  0.1U_0201_6.3V6K  [C_0201]  133.01 34.38 0 top
CC302  0.1U_0201_6.3V6K  [C_0201]  139 32.29 180 top
CC303  1U_0402_6.3V6K  [C_0402]  94.48 109.82 0 top
CD1  10U_0603_6.3V6M~D  [C_0603]  115.71 62.98 180 top
CD2  10U_0603_6.3V6M~D  [C_0603]  115.71 64.25 180 top
CD3  1U_0402_6.3V6K~D  [C_0402]  115.45 60.94 180 top
CD4  1U_0402_6.3V6K~D  [C_0402]  115.45 61.89 180 top
CD5  1U_0402_6.3V6K~D  [C_0402]  111.01 60.08 180 top
CD6  10U_0603_6.3V6M~D  [C_0603]  111.41 58.98 180 top
CD7  10U_0603_6.3V6M~D  [C_0603]  111.4 57.73 180 top
CD9  0.1U_0402_16V7K~D  [C_0402]  105.58 73.06 270 top
CD10  2.2U_0603_6.3V6K~D  [C_0603]  106.68 73.08 270 top
CD11  1U_0402_6.3V6K~D  [C_0402]  57.42 62.49 90 top
CD12  1U_0402_6.3V6K~D  [C_0402]  53.21 73.28 270 top
CD13  1U_0402_6.3V6K~D  [C_0402]  72.07 73.22 270 top
CD14  1U_0402_6.3V6K~D  [C_0402]  74.07 72.29 90 top
CD15  1U_0402_6.3V6K~D  [C_0402]  46.75 62.49 90 top
CD16  1U_0402_6.3V6K~D  [C_0402]  78 72.9 270 top
CD17  1U_0402_6.3V6K~D  [C_0402]  83.03 68.5 270 top
CD18  1U_0402_6.3V6K~D  [C_0402]  86.28 72.64 0 top
CD19  10U_0603_6.3V6M~D  [C_0603]  83.14 61.19 90 top
CD20  10U_0603_6.3V6M~D  [C_0603]  73.93 61.99 90 top
CD21  10U_0603_6.3V6M~D  [C_0603]  64.9 73.4 270 top
CD22  10U_0603_6.3V6M~D  [C_0603]  72.07 69.68 270 top
CD23  10U_0603_6.3V6M~D  [C_0603]  76.18 73.11 270 top
CD24  10U_0603_6.3V6M~D  [C_0603]  85.69 71.62 270 top
CD25  10U_0603_6.3V6M~D  [C_0603]  95.78 71.77 270 top
CD26  10U_0603_6.3V6M~D  [C_0603]  103.53 71.89 270 top
CD27  330U_D2_2V_Y  [C_D2]  90.32 87.2 0 top
CD28  0.1U_0402_16V7K~D  [C_0402]  85.36 63.07 180 top
CD29  0.1U_0402_16V7K~D  [C_0402]  82.89 60.27 270 top
CD30  0.022U_0402_25V7K  [C_0402]  82.01 63.69 180 top
CD31  1U_0402_6.3V6K~D  [C_0402]  115.97 52.27 270 top
CD32  10U_0603_6.3V6M~D  [C_0603]  117.12 52.25 270 top
CD33  10U_0603_6.3V6M~D  [C_0603]  118.39 52.25 270 top
CD34  10U_0603_6.3V6M~D  [C_0603]  119.62 52.48 270 top
CD35  1U_0402_6.3V6K~D  [C_0402]  117.1 59.92 270 top
CD36  1U_0402_6.3V6K~D  [C_0402]  119.15 58.77 180 top
CD37  10U_0603_6.3V6M~D  [C_0603]  119.51 57.71 180 top
CD39  0.1U_0402_16V7K~D  [C_0402]  115.19 56.84 0 top
CD40  2.2U_0603_6.3V6K~D  [C_0603]  114.95 57.95 0 top
CD41  1U_0402_6.3V6K~D  [C_0402]  61.47 52.88 180 top
CD42  1U_0402_6.3V6K~D  [C_0402]  72.54 61.11 270 top
CD43  1U_0402_6.3V6K~D  [C_0402]  83.29 52.98 90 top
CD44  1U_0402_6.3V6K~D  [C_0402]  77.69 58.83 270 top
CD45  1U_0402_6.3V6K~D  [C_0402]  79.27 60.96 90 top
CD46  1U_0402_6.3V6K~D  [C_0402]  73.94 60.35 270 top
CD47  1U_0402_6.3V6K~D  [C_0402]  94.03 52.37 90 top
CD48  1U_0402_6.3V6K~D  [C_0402]  93.26 48.02 0 top
CD49  10U_0603_6.3V6M~D  [C_0603]  75.21 58.81 270 top
CD50  10U_0603_6.3V6M~D  [C_0603]  81 58.82 270 top
CD51  10U_0603_6.3V6M~D  [C_0603]  80.99 60.86 90 top
CD52  10U_0603_6.3V6M~D  [C_0603]  79.66 58.81 270 top
CD53  10U_0603_6.3V6M~D  [C_0603]  70.22 61.11 270 top
CD54  10U_0603_6.3V6M~D  [C_0603]  59.21 51.57 270 top
CD55  10U_0603_6.3V6M~D  [C_0603]  68.1 61.1 270 top
CD56  10U_0603_6.3V6M~D  [C_0603]  64.48 60.44 270 top
CD58  0.1U_0402_16V7K~D  [C_0402]  90.51 47.35 0 top
CD59  0.022U_0402_25V7K  [C_0402]  88.72 53.03 0 top
CD60  1U_0402_6.3V6K~D  [C_0402]  112.85 58.37 0 top
CD61  1U_0402_6.3V6K~D  [C_0402]  112.85 59.26 0 top
CD62  1U_0402_6.3V6K~D  [C_0402]  114.3 66.19 270 top
CD63  1U_0402_6.3V6K~D  [C_0402]  119.23 56.59 180 top
CE1  0.1U_0402_10V7K  [C_0402]  93.68 34.36 0 top
CE2  0.1U_0402_10V7K  [C_0402]  93.68 36.23 0 top
CE3  10P_0402_50V8J  [C_0402]  95.08 43.22 270 top
CE4  12P_0402_50V8J  [C_0402]  94.89 44.07 90 top
CE5  10U_0603_6.3V6M  [C_0603]  66.98 48.51 0 top
CE6  0.1U_0402_10V7K  [C_0402]  70.41 47.79 90 top
CE7  1000P_0402_50V7K  [C_0402]  69.46 48.71 270 top
CE8  1000P_0402_50V7K  [C_0402]  82.03 48.2 270 top
CE9  0.1U_0402_25V6  [C_0402]  88.16 47.34 90 top
CE10  0.1U_0402_25V6  [C_0402]  83.92 28.01 180 top
CE11  0.1U_0402_25V6  [C_0402]  73 39.06 180 top
CE12  0.1U_0402_25V6  [C_0402]  73.34 28.4 180 top
CE13  0.1U_0402_25V6  [C_0402]  92.28 33.35 0 top
CE14  0.1U_0402_10V7K  [C_0402]  92.28 40.89 0 top
CE15  0.1U_0402_25V6  [C_0402]  72.13 35.72 90 top
CE16  100P_0402_50V8J  [C_0402]  73.09 47.79 90 top
CE17  0.1U_0402_25V6  [C_0402]  89.81 28.01 0 top
CE19  0.047U_0402_16V4Z  [C_0402]  73.19 26.59 270 top
CE20  0.1U_0402_25V6  [C_0402]  79.72 47.24 90 top
CE21  0.1U_0402_25V6  [C_0402]  92.91 38.7 0 top
CE22  0.1U_0402_10V7K  [C_0402]  68.68 33.25 180 top
CE23  0.1U_0402_25V6  [C_0402]  77.1 47.26 90 top
CE24  1U_0603_16V7  [C_0603]  83.11 47.36 90 top
CE25  2200P_0402_25V7K  [C_0402]  94.27 35.34 0 top
CE26  47P_0402_50V8J  [C_0402]  68.68 34.14 180 top
CE28  220P_0402_50V8J  [C_0402]  71.27 40.08 180 top
CE30  2200P_0402_25V7K  [C_0402]  95.66 37.46 90 top
CE31  1000P_0402_50V7K  [C_0402]  78.05 26.57 270 top
CE32  100P_0402_50V8J  [C_0402]  93.32 43.51 180 top
CE33  2.2U_0402_6.3V6M  [C_0402]  92.41 44.94 0 top
CE34  100P_0402_50V8J  [C_0402]  78.78 48.16 270 top
CE35  33P_0402_50V8J  [C_0402-NPM]  72.93 39.22 270 bottom
CE36  68P_0201_50V8J  [C_0201]  73.17 29.75 180 top
CE37  10P_0201_50V8J  [C_0201]  73.2 29.16 180 top
CE38  68P_0201_50V8J  [C_0201]  70.75 35.86 90 top
CE39  10P_0201_50V8J  [C_0201]  71.38 35.86 90 top
CE99  0.01U_0402_16V7K  [C_0402]  121.83 61.12 0 bottom
CE100  0.01U_0402_16V7K  [C_0402]  279.86 55.66 180 top
CG47  0.1U_0402_10V7K  [C_0402]  212.25 101.8 180 top
CG48  0.1U_0402_10V7K  [C_0402]  214.39 99.23 270 top
CG64  220P_0402_50V8J  [C_0402]  196.03 126.55 90 bottom
CG65  220P_0402_50V8J  [C_0402]  195.01 126.55 90 bottom
CG246  0.1U_0201_6.3V6K  [C_0201]  239.22 89.87 180 bottom
CG288  22U_0603_6.3V6M  [C_0603]  198.12 123.13 90 bottom
CG289  10U_0603_6.3V6M  [C_0603]  193.36 122.62 90 bottom
CG290  10U_0603_6.3V6M  [C_0603]  193.92 126.21 90 bottom
CG310  1U_0402_6.3V6K  [C_0402]  212.51 98.73 270 top
CG320  10U_0603_6.3V6M  [C_0603]  197.1 126.31 90 bottom
CG386  0.1U_0402_10V7K  [C_0402]  196.13 121.43 270 bottom
CG438  0.1U_0201_6.3V6K  [C_0201]  199.87 122.52 90 bottom
CG440  0.1U_0201_6.3V6K  [C_0201]  241.32 81.97 270 bottom
CG442  2200P_0402_25V7K  [C_0402]  198.91 93.86 270 bottom
CG482  0.047U_0402_16V4Z  [C_0402]  198.01 89.93 90 bottom
CG487  0.1U_0402_10V7K  [C_0402]  194.35 121.43 270 bottom
CG527  0.1U_0201_6.3V6K  [C_0201]  204.66 91.56 0 bottom
CH12  22U_0402_6.3V6M  [C_0402]  171.85 43.54 180 top
CH13  1U_0402_6.3V6K  [C_0402]  171.81 42.64 180 top
CH14  0.1U_0402_10V6K  [C_0402]  169.3 43.77 270 top
CH15  0.1U_0402_10V6K  [C_0402]  171.43 41.78 270 top
CH16  1U_0402_6.3V6K  [C_0402]  187.62 34.3 180 top
CH17  1P_0402_50V8  [C_0402]  157.07 56.45 270 bottom
CH18  22U_0402_6.3V6M  [C_0402]  164.05 32.49 90 top
CH19  1U_0402_6.3V6K  [C_0402]  164.96 32.47 90 top
CH20  22U_0402_6.3V6M  [C_0402]  170.12 59.31 0 bottom
CH21  1U_0402_6.3V6K  [C_0402]  158.86 56.52 270 bottom
CH22  0.1U_0402_10V6K  [C_0402]  171.23 46.3 90 top
CH23  1U_0402_6.3V6K  [C_0402]  160.68 56.52 270 bottom
CH24  1P_0402_50V8  [C_0402]  155.25 56.42 270 bottom
CH25  0.1U_0402_10V6K  [C_0402]  186.5 33.43 270 top
CH29  1U_0402_6.3V6K  [C_0402]  177.08 45.97 0 top
CH30  0.1U_0402_10V6K  [C_0402]  182.6 51.89 180 top
CH31  1U_0402_6.3V6K  [C_0402]  189.33 52.13 90 top
CH32  0.1U_0402_10V6K  [C_0402]  172.98 44.48 180 top
CH33  0.1U_0402_10V6K  [C_0402]  178.7 43.42 270 top
CH34  0.1U_0402_10V6K  [C_0402]  185.84 30.77 0 top
CH35  4.7U_0402_6.3V6M  [C_0402]  180.81 49.25 90 top
CH36  4.7U_0402_6.3V6M  [C_0402]  190.03 58.96 90 bottom
CH45  8.2P_0402_50V  [C_0402]  179.81 30.43 0 top
CH46  8.2P_0402_50V  [C_0402]  178.94 30.43 180 top
CH47  15P_0402_50V  [C_0402]  155.7 51.1 0 bottom
CH48  15P_0402_50V  [C_0402]  154.81 51.13 180 bottom
CH49  0.1U_0402_16V7K  [C_0402]  213.16 40.53 0 bottom
CH51  10P_0402_25V8J  [C_0402]  191.03 59.89 270 bottom
CH52  1U_0603_10V6K~D  [C_0603]  188.57 33.93 0 top
CH53  1U_0603_10V6K~D  [C_0603]  176.43 26.11 270 top
CH62  1U_0402_6.3V6K  [C_0402]  174.75 46.67 0 top
CH63  1P_0402_50V8  [C_0402]  179.1 40 180 top
CH197  0.1U_0402_10V7K  [C_0402]  55.88 108.66 90 bottom
CH201  0.1U_0201_6.3V6K  [C_0201]  194.76 29.98 180 top
CH209  100P_0402_50V8J  [C_0402]  183.72 58.97 90 bottom
CH210  100P_0402_50V8J  [C_0402]  104.93 116.97 90 top
CH211  100P_0402_50V8J  [C_0402]  64.33 120.74 0 top
CH212  100P_0402_50V8J  [C_0402]  182.49 30.67 180 top
CH222  100P_0402_50V8J  [C_0402]  193.83 29.68 90 bottom
CH223  1U_0402_6.3V6K  [C_0402]  156.17 56.45 270 bottom
CH224  33P_0402_50V8J  [C_0402]  213.19 44.11 270 bottom
CH225  0.1U_0402_10V6K  [C_0402]  179.3 26.2 270 top
CH226  1U_0402_6.3V6K  [C_0402]  180.2 26.19 270 top
CH228  0.1U_0402_10V7K  [C_0402]  169.75 28.98 180 top
CL1  .1U_0402_16V7K  [C_0402]  62.15 35.65 0 top
CL2  .1U_0402_16V7K  [C_0402]  62.15 36.54 0 top
CL3  .1U_0402_16V7K  [C_0402]  59.13 34.64 270 top
CL4  .1U_0402_16V7K  [C_0402]  60.02 34.64 270 top
CL5  .1U_0402_16V7K  [C_0402]  55.4 44.96 90 top
CL6  .1U_0402_16V7K  [C_0402]  53 40.9 180 top
CL7  .1U_0402_16V7K  [C_0402]  57.35 35.2 270 top
CL8  .1U_0402_16V7K  [C_0402]  62.26 40.7 90 top
CL9  1U_0402_6.3V6K  [C_0402]  41.55 34.73 180 top
CL10  10P_0402_50V8J  [C_0402]  58.48 44.68 270 top
CL11  10P_0402_50V8J  [C_0402]  57.52 44.68 270 top
CL12  0.01U_0402_50V7K  [C_0402]  26.07 76.28 180 top
CL13  100P_1206_2KV8J  [C_1206]  18.91 82.6 0 bottom
CL15  .1U_0402_16V7K  [C_0402]  62.44 42.74 0 top
CL18  .1U_0402_16V7K  [C_0402]  54.45 37.84 180 top
CL19  .1U_0402_16V7K  [C_0402]  54.45 36.96 180 top
CL20  .1U_0402_16V7K  [C_0402]  54.63 42.49 180 top
CL22  1U_0402_10V6K  [C_0402]  62.29 38.61 0 top
CL23  .1U_0402_16V7K  [C_0402]  62.29 39.5 0 top
CL24  4.7U_0603_6.3V6K  [C_0603]  55.49 35.09 270 top
CL25  4.7U_0603_6.3V6K  [C_0603]  53.31 44.76 90 top
CLIP1  CLIP_15X3_VIUS1  [CLIP_15X3]  161.99 46.73 0 top
CLIP2  -  [CLIP_10P2X7P2_SHIELDING_CASE1]  15.9 111.4 180 bottom
CLRP1  SHORT PADS  [SHORTPADS]  90.18 33.55 270 bottom
CP3  0.01U_0402_16V7K  [C_0402]  22.83 89.13 180 top
CP4  0.1U_0201_6.3V6K  [C_0201]  22.69 88.38 180 top
CP5  0.1U_0201_6.3V6K  [C_0201]  23.42 97.95 270 bottom
CP6  0.1U_0201_6.3V6K  [C_0201]  21.12 98.69 180 top
CP7  0.01U_0402_16V7K  [C_0402]  22.5 99.57 90 top
CP8  4.7U_0603_6.3V6K  [C_0603]  27.77 99.29 0 top
CP9  0.1U_0201_6.3V6K  [C_0201]  26.82 95.58 180 bottom
CP10  0.1U_0201_6.3V6K  [C_0201]  26.7 94.31 180 bottom
CP11  0.01U_0402_16V7K  [C_0402]  27.78 98.21 0 top
CP12  0.1U_0201_6.3V6K  [C_0201]  21.39 97.38 270 bottom
CP13  0.1U_0201_6.3V6K  [C_0201]  18.02 94.96 180 top
CP14  0.01U_0402_16V7K  [C_0402]  22.25 90.4 180 bottom
CP15  0.1U_0201_6.3V6K  [C_0201]  29.27 92.02 180 top
CP16  0.1U_0201_6.3V6K  [C_0201]  29.27 92.66 180 top
CP17  0.1U_0201_6.3V6K  [C_0201]  29.27 93.29 180 top
CP18  0.1U_0201_6.3V6K  [C_0201]  29.27 93.93 180 top
CP19  0.1U_0201_6.3V6K  [C_0201]  29.27 94.69 180 top
CP20  0.1U_0201_6.3V6K  [C_0201]  29.27 95.32 180 top
CP21  0.1U_0201_6.3V6K  [C_0201]  29.27 95.96 180 top
CP22  0.1U_0201_6.3V6K  [C_0201]  29.27 96.59 180 top
CP23  0.1U_0201_6.3V6K  [C_0201]  20.49 95.71 90 bottom
CP24  0.1U_0201_6.3V6K  [C_0201]  21.09 91.38 0 bottom
CP25  0.01U_0402_16V7K  [C_0402]  20.21 87.35 0 top
CP26  0.1U_0201_6.3V6K  [C_0201]  25.35 97.38 270 bottom
CP27  1U_0402_6.3V6K  [C_0402]  26.42 87.16 270 top
CP28  10U_0603_6.3V6M  [C_0603]  22.03 85.48 180 bottom
CP29  1U_0603_6.3V6M  [C_0603]  23.98 83.88 270 bottom
CP32  10U_0603_6.3V6M  [C_0603]  21.18 87.16 180 bottom
CS1  0.01U_0201_16V7  [C_0201]  269.82 41.31 0 top
CS2  0.01U_0201_16V7  [C_0201]  269.82 40.68 0 top
CS3  0.01U_0201_16V7  [C_0201]  269.82 39.76 0 top
CS4  0.01U_0201_16V7  [C_0201]  269.82 39.13 0 top
CS5  1000P_0402_50V7K  [C_0402]  275.87 36.24 0 top
CS6  0.1U_0402_25V6K  [C_0402]  275.86 35.33 0 top
CS7  10U_0805_10V6K  [C_0805]  275.74 34 0 top
CS8  1U_0402_10V6K  [C_0402]  275.81 40.84 90 top
CS16  0.22U_0402_16V7K  [C_0402]  36.68 30.64 90 top
CS17  0.22U_0402_16V7K  [C_0402]  35.73 30.64 90 top
CS18  0.22U_0402_16V7K  [C_0402]  34.13 30.64 90 top
CS19  0.22U_0402_16V7K  [C_0402]  33.17 30.64 90 top
CS20  0.22U_0402_16V7K  [C_0402]  31.14 30.64 90 top
CS21  0.22U_0402_16V7K  [C_0402]  30.19 30.64 90 top
CS22  0.22U_0402_16V7K  [C_0402]  28.09 30.64 90 top
CS23  0.22U_0402_16V7K  [C_0402]  27.14 30.64 90 top
CS24  10U_0805_25V6K~D  [C_0805]  42.11 26.58 270 top
CS25  1U_0402_6.3V6K~D  [C_0402]  35.71 27.3 0 top
CS26  0.1U_0402_25V6K~D  [C_0402]  22.73 25.24 0 top
CS27  1000P_0402_50V7K~D  [C_0402]  35.71 26.41 0 top
CS29  0.1U_0402_25V6K  [C_0402]  192.34 51.93 180 top
CS30  10U_0805_10V6K  [C_0805]  195.86 49.97 90 bottom
CS32  68P_0201_50V8J  [C_0201]  275.97 36.99 0 top
CS33  47U_0805_6.3V6M  [C_0805]  43.88 26.58 270 top
CS34  47U_0805_6.3V6M  [C_0805]  45.66 26.58 270 top
CS35  22U_0603_6.3V6M  [C_0603]  40.62 26.63 270 top
CS36  22U_0603_6.3V6M  [C_0603]  22.74 24.09 0 top
CT1  0.22U_0201_6.3V  [C_0201]  26.89 119.92 90 bottom
CT2  0.22U_0201_6.3V  [C_0201]  26.25 119.92 90 bottom
CT3  0.22U_0201_6.3V  [C_0201]  29.43 119.92 90 bottom
CT4  0.22U_0201_6.3V  [C_0201]  24.98 119.92 90 bottom
CT5  0.22U_0201_6.3V  [C_0201]  22.44 119.92 90 bottom
CT12  0.22U_0201_6.3V  [C_0201]  25.62 119.92 90 bottom
CT13  0.22U_0201_6.3V  [C_0201]  27.52 119.92 90 bottom
CT14  0.22U_0201_6.3V  [C_0201]  28.16 119.92 90 bottom
CT15  0.22U_0201_6.3V  [C_0201]  30.06 119.92 90 bottom
CT16  0.22U_0201_6.3V  [C_0201]  28.79 119.92 90 bottom
CT18  0.22U_0201_6.3V  [C_0201]  24.35 119.92 90 bottom
CT21  0.22U_0201_6.3V  [C_0201]  21.81 119.92 90 bottom
CT37  27P_0402_50V8J  [C_0402]  17.73 113.28 90 bottom
CT38  27P_0402_50V8J  [C_0402]  17.73 115.06 90 bottom
CT39  0.22U_0201_6.3V  [C_0201]  16.69 125.54 0 top
CT40  0.22U_0201_6.3V  [C_0201]  16.69 124.96 0 top
CT41  0.22U_0201_6.3V  [C_0201]  16.78 123.7 0 bottom
CT42  0.22U_0201_6.3V  [C_0201]  16.78 124.33 0 bottom
CT43  0.1U_0201_6.3V6K  [C_0201]  29.73 125.96 180 top
CT44  0.1U_0201_6.3V6K  [C_0201]  29.73 126.53 180 top
CT45  0.1U_0201_6.3V6K  [C_0201]  15.65 87.83 270 bottom
CT46  0.1U_0201_6.3V6K  [C_0201]  26.85 129.8 0 top
CT47  1U_0201_6.3V6M  [C_0201]  21.64 130.31 180 top
CT48  1U_0201_6.3V6M  [C_0201]  22.95 128.37 90 top
CT49  1U_0201_6.3V6M  [C_0201]  28.9 130.46 0 top
CT50  10U_0402_6.3V6M  [C_0402]  12.78 131.5 0 bottom
CT51  10U_0402_6.3V6M  [C_0402]  14.69 130.64 90 bottom
CT52  10U_0402_6.3V6M  [C_0402]  15.58 130.64 90 bottom
CT53  10U_0402_6.3V6M  [C_0402]  16.47 130.64 90 bottom
CT54  1U_0201_6.3V6M  [C_0201]  26.84 126.58 0 top
CT55  1U_0201_6.3V6M  [C_0201]  24.38 122.69 180 top
CT56  1U_0201_6.3V6M  [C_0201]  26.8 124.53 180 top
CT57  1U_0201_6.3V6M  [C_0201]  24.24 127.14 0 top
CT58  1U_0201_6.3V6M  [C_0201]  23.77 129.63 270 top
CT59  1U_0201_6.3V6M  [C_0201]  24.51 130.38 180 top
CT60  1U_0201_6.3V6M  [C_0201]  15.95 128.12 90 top
CT61  1U_0201_6.3V6M  [C_0201]  16.52 128.12 90 top
CT62  1U_0201_6.3V6M  [C_0201]  17.09 128.12 90 top
CT63  1U_0201_6.3V6M  [C_0201]  24.47 129.04 0 top
CT64  1U_0201_6.3V6M  [C_0201]  24.94 128.34 0 top
CT65  1U_0201_6.3V6M  [C_0201]  20.47 127.99 90 top
CT66  1U_0201_6.3V6M  [C_0201]  19.9 127.99 90 top
CT67  1U_0201_6.3V6M  [C_0201]  19.24 128.03 180 top
CT68  1U_0201_6.3V6M  [C_0201]  20.47 127.24 270 top
CT69  1U_0201_6.3V6M  [C_0201]  19.9 127.24 270 top
CT70  1U_0201_6.3V6M  [C_0201]  25.61 122.72 90 top
CT71  1U_0201_6.3V6M  [C_0201]  25.01 124.53 0 top
CT72  1U_0201_6.3V6M  [C_0201]  24.38 123.26 180 top
CT73  47U_0603_6.3V6M  [C_0603]  14.85 133.39 0 top
CT74  47U_0603_6.3V6M  [C_0603]  14.85 134.61 0 top
CT75  47U_0603_6.3V6M  [C_0603]  14.86 135.82 0 top
CT77  1U_0201_6.3V6M  [C_0201]  27.52 124.63 270 top
CT78  1U_0201_6.3V6M  [C_0201]  26.85 129.23 0 top
CT79  1U_0201_6.3V6M  [C_0201]  25.55 127.24 270 top
CT80  1U_0201_6.3V6M  [C_0201]  26.34 128.4 0 top
CT81  10U_0402_6.3V6M  [C_0402]  19.65 124.16 270 top
CT82  10U_0402_6.3V6M  [C_0402]  19.65 125.03 90 top
CT83  1U_0201_6.3V6M  [C_0201]  22.47 124.53 0 top
CT84  1U_0201_6.3V6M  [C_0201]  22.44 127.75 270 top
CT85  1U_0201_6.3V6M  [C_0201]  22.22 125.91 180 top
CT86  1U_0201_6.3V6M  [C_0201]  22.88 126.5 180 top
CT88  0.1U_0402_10V6K  [C_0402]  31.36 90.85 180 top
CT90  22U_0603_6.3V6M  [C_0603]  32.92 84.36 270 bottom
CT91  22U_0603_6.3V6M  [C_0603]  31.71 84.36 270 bottom
CT92  22U_0603_6.3V6M  [C_0603]  30.51 84.36 270 bottom
CT93  22U_0603_6.3V6M  [C_0603]  29.3 84.36 270 bottom
CT94  0.01U_0402_50V7K  [C_0402]  11.15 122.17 90 bottom
CT95  0.01U_0402_50V7K  [C_0402]  10.26 122.17 90 bottom
CT96  0.01U_0402_50V7K  [C_0402]  11.02 121.28 270 bottom
CT97  0.01U_0402_50V7K  [C_0402]  11.91 121.28 270 bottom
CT98  2.2U_0603_16V6K  [C_0603]  31.7 92.76 90 bottom
CT99  4.7U_0603_10V6K  [C_0603]  29.41 92.38 180 bottom
CT100  4.7U_0603_10V6K  [C_0603]  38.56 91.83 0 top
CT101  1U_0402_6.3V6K  [C_0402]  35.01 93.49 90 bottom
CT102  1U_0201_6.3V6M  [C_0201]  36.6 92.52 270 top
CT103  10U_0402_6.3V6M  [C_0402]  33.95 92.6 0 top
CT104  0.22U_0402_10V4Z  [C_0402]  35.71 87.93 270 top
CT106  1U_0603_25V6K  [C_0603]  28.89 85.5 180 bottom
CT108  0.22U_0201_6.3V  [C_0201]  23.08 119.92 90 bottom
CT109  0.22U_0201_6.3V  [C_0201]  23.71 119.92 90 bottom
CT110  0.22U_0201_6.3V  [C_0201]  20.54 119.92 90 bottom
CT111  0.22U_0201_6.3V  [C_0201]  21.17 119.92 90 bottom
CT112  220P_0201_25V7K  [C_0201]  37.43 86.44 0 bottom
CT113  220P_0201_25V7K  [C_0201]  37.41 85.83 0 bottom
CT117  0.1U_0201_6.3V6K  [C_0201]  32.21 129.95 180 bottom
CT118  0.1U_0201_6.3V6K  [C_0201]  32.21 129.38 180 bottom
CT119  0.1U_0201_6.3V6K  [C_0201]  32.73 128.49 180 bottom
CT120  0.1U_0201_6.3V6K  [C_0201]  32.73 127.92 180 bottom
CT121  0.1U_0201_6.3V6K  [C_0201]  33.48 127.31 180 bottom
CT122  0.1U_0201_6.3V6K  [C_0201]  33.48 126.74 180 bottom
CT123  0.1U_0201_6.3V6K  [C_0201]  32.21 125.7 180 bottom
CT124  0.1U_0201_6.3V6K  [C_0201]  32.21 126.27 180 bottom
CT125  0.1U_0201_6.3V6K  [C_0201]  30.03 128.42 180 top
CT126  0.1U_0201_6.3V6K  [C_0201]  30.03 129.01 180 top
CT137  0.1U_0201_6.3V6K  [C_0201]  34.7 91.26 0 top
CT153  1U_0201_6.3V6M  [C_0201]  31.62 125.07 0 bottom
CT154  47U_0603_6.3V6M  [C_0603]  31.61 124.09 0 bottom
CT155  47U_0603_6.3V6M  [C_0603]  31.61 122.82 0 bottom
CT156  33P_0402_50V8J  [C_0402]  35.71 71.61 0 bottom
CT157  33P_0402_50V8J  [C_0402]  32.67 118.59 270 top
CTPM1  0.1U_0402_16V7K  [C_0402]  207.21 32.88 180 top
CTPM2  10U_0402_6.3V6M  [C_0402]  205.38 32 90 top
CTPM3  0.1U_0402_10V7K  [C_0402]  204.8 38.2 270 top
CTPM4  10U_0402_6.3V6M  [C_0402]  203.87 38.19 270 top
CTPM5  10U_0402_6.3V6M  [C_0402]  192.58 31.81 270 top
CTPM6  0.1U_0402_10V7K  [C_0402]  202.08 36.74 0 top
CTPM7  0.1U_0402_10V7K  [C_0402]  193.51 31.82 270 top
CU1  .1U_0402_16V7K  [C_0402]  20.36 45.05 90 top
CU2  .1U_0402_16V7K  [C_0402]  19.4 45.05 90 top
CU3  .1U_0402_16V7K  [C_0402]  28.94 28.38 180 top
CU4  .1U_0402_16V7K  [C_0402]  28.94 27.43 180 top
CU5  1U_0402_10V6K  [C_0402]  27.33 35.1 270 top
CU6  1U_0402_10V6K  [C_0402]  18.05 57.73 0 top
CU7  1U_0402_10V6K  [C_0402]  18.05 58.68 0 top
CU8  22U_0805_10V6M  [C_0805]  19.73 58.04 0 bottom
CU9  22U_0805_10V6M  [C_0805]  19.73 59.75 0 bottom
CU10  100U_1206_6.3V6M  [C_1206]  18.85 61.8 0 bottom
CU11  1U_0402_10V6K  [C_0402]  22.17 32.78 0 top
CU12  1U_0402_10V6K  [C_0402]  22.17 31.86 0 top
CU13  22U_0805_10V6M  [C_0805]  21.43 34.33 90 top
CU14  22U_0805_10V6M  [C_0805]  19.7 34.33 90 top
CU15  100U_1206_6.3V6M  [C_1206]  18.79 38.14 0 bottom
CU16  1U_0402_10V6K  [C_0402]  271.45 30.46 270 top
CU17  22U_0805_10V6M  [C_0805]  268.22 33.01 0 top
CU19  10P_0201_50V8J  [C_0201]  22.58 33.65 0 top
CU20  68P_0201_50V8J  [C_0201]  18.23 56.95 0 top
CU21  10P_0201_50V8J  [C_0201]  267.09 34.19 180 top
CU22  68P_0201_50V8J  [C_0201]  267.09 34.83 180 top
CV50  22U_0603_6.3V6M  [C_0603]  207.42 98.16 270 top
CV51  4.7U_0603_6.3V6K  [C_0603]  206.19 99.1 270 top
CV52  0.1U_0402_10V7K  [C_0402]  209.31 99.91 90 top
CV53  0.1U_0402_10V7K  [C_0402]  209.31 99.04 270 top
CV70  10P_0402_50V8J  [C_0402]  230.02 91.35 180 bottom
CV71  10P_0402_50V8J  [C_0402]  227.26 91.35 0 bottom
CV72  0.1U_0402_10V7K  [C_0402]  215.2 101.15 0 top
CV79  10U_0603_6.3V6M  [C_0603]  204.24 115.45 90 top
CV80  10U_0603_6.3V6M  [C_0603]  219.98 114.25 90 top
CV83  22U_0603_6.3V6M  [C_0603]  201.31 119.04 90 top
CV84  22U_0603_6.3V6M  [C_0603]  224.18 115.53 270 top
CV85  22U_0603_6.3V6M  [C_0603]  206.78 116.85 270 top
CV86  22U_0603_6.3V6M  [C_0603]  205.51 116.85 270 top
CV87  1U_0402_6.3V6K  [C_0402]  213.49 112.35 0 top
CV88  1U_0402_6.3V6K  [C_0402]  213.49 113.25 0 top
CV89  1U_0402_6.3V6K  [C_0402]  213.01 115.39 0 top
CV90  1U_0402_6.3V6K  [C_0402]  211.8 113.61 180 top
CV91  4.7U_0603_6.3V6K  [C_0603]  213.05 109.45 0 top
CV92  4.7U_0603_6.3V6K  [C_0603]  213.1 114.35 0 top
CV93  10U_0603_6.3V6M  [C_0603]  210.51 111.04 0 top
CV94  10U_0603_6.3V6M  [C_0603]  214.3 106 180 top
CV95  10U_0603_6.3V6M  [C_0603]  203.68 114.45 90 bottom
CV96  22U_0603_6.3V6M  [C_0603]  212.93 111.16 0 top
CV97  22U_0603_6.3V6M  [C_0603]  208.92 115.18 270 top
CV100  1U_0402_6.3V6K  [C_0402]  215.45 115.61 270 top
CV101  1U_0402_6.3V6K  [C_0402]  226.73 107.02 180 top
CV102  1U_0402_6.3V6K  [C_0402]  226.73 107.91 180 top
CV103  1U_0402_6.3V6K  [C_0402]  226.97 104.48 180 top
CV112  1U_0402_6.3V6K  [C_0402]  228.52 111.2 0 top
CV113  1U_0402_6.3V6K  [C_0402]  228.58 103.64 90 top
CV114  0.1U_0402_10V7K  [C_0402]  211.63 103.57 90 top
CV117  0.1U_0402_10V7K  [C_0402]  224.24 100.94 180 top
CV118  0.1U_0402_10V7K  [C_0402]  224.24 99.98 180 top
CV119  1U_0402_6.3V6K  [C_0402]  224.3 98.65 180 top
CV120  4.7U_0603_6.3V6K  [C_0603]  222.89 96.81 0 top
CV152  0.1U_0402_10V7K  [C_0402]  224.78 117.34 90 top
CV153  0.1U_0402_10V7K  [C_0402]  228.55 107.06 270 top
CV154  0.1U_0402_10V7K  [C_0402]  221.47 116.97 0 top
CV156  22U_0603_6.3V6M  [C_0603]  207.66 112.65 0 top
CV158  820P_0402_25V7  [C_0402]  237.86 143.72 90 bottom
CV160  10U_0603_6.3V6M  [C_0603]  222.49 149.64 90 bottom
CV161  10U_0603_6.3V6M  [C_0603]  222.55 139.03 270 bottom
CV162  10U_0603_6.3V6M  [C_0603]  238.05 138.27 270 bottom
CV163  10U_0603_6.3V6M  [C_0603]  238.11 149.89 90 bottom
CV164  10U_0603_6.3V6M  [C_0603]  237.6 142.15 270 top
CV165  1U_0402_6.3V6K  [C_0402]  227.13 151.59 90 top
CV166  1U_0402_6.3V6K  [C_0402]  225.54 145.46 270 top
CV167  1U_0402_6.3V6K  [C_0402]  233.73 151.59 90 top
CV168  10U_0603_6.3V6M  [C_0603]  217.38 138.78 270 bottom
CV169  10U_0603_6.3V6M  [C_0603]  201.95 138.02 270 bottom
CV170  10U_0603_6.3V6M  [C_0603]  209.7 151.23 90 top
CV171  10U_0603_6.3V6M  [C_0603]  217.45 149.57 90 bottom
CV172  10U_0603_6.3V6M  [C_0603]  201.89 150.02 90 bottom
CV173  1U_0402_6.3V6K  [C_0402]  203.6 143.34 90 top
CV174  1U_0402_6.3V6K  [C_0402]  210.35 146.92 270 top
CV175  1U_0402_6.3V6K  [C_0402]  202.52 148.13 270 top
CV177  820P_0402_25V7  [C_0402]  256.3 92.18 0 bottom
CV179  10U_0603_6.3V6M  [C_0603]  250.95 111.13 180 bottom
CV180  10U_0603_6.3V6M  [C_0603]  265.01 95.07 180 top
CV181  10U_0603_6.3V6M  [C_0603]  263.49 99.86 0 top
CV182  10U_0603_6.3V6M  [C_0603]  257.71 107.1 0 top
CV183  10U_0603_6.3V6M  [C_0603]  261.97 107.1 0 top
CV184  1U_0402_6.3V6K  [C_0402]  260.05 107.1 0 top
CV185  1U_0402_6.3V6K  [C_0402]  263.8 102.34 0 top
CV186  1U_0402_6.3V6K  [C_0402]  258.87 100.69 180 top
CV187  10U_0603_6.3V6M  [C_0603]  250.03 128.05 180 bottom
CV188  10U_0603_6.3V6M  [C_0603]  261.71 113 0 top
CV189  10U_0603_6.3V6M  [C_0603]  263.18 120.24 0 top
CV190  10U_0603_6.3V6M  [C_0603]  257.52 112.93 0 top
CV191  10U_0603_6.3V6M  [C_0603]  258.73 127.6 180 top
CV192  1U_0402_6.3V6K  [C_0402]  258.87 119.41 180 top
CV193  1U_0402_6.3V6K  [C_0402]  258.95 121.19 180 top
CV194  1U_0402_6.3V6K  [C_0402]  259.95 127.92 180 bottom
CV199  820P_0402_25V7  [C_0402]  256.27 127.92 180 bottom
CV200  820P_0402_25V7  [C_0402]  201.95 144.04 90 bottom
CV202  0.1U_0402_10V7K  [C_0402]  225.87 100.01 270 top
CV206  1U_0402_6.3V6K  [C_0402]  226 114.87 225 top
CV207  1U_0402_6.3V6K  [C_0402]  227.46 112.35 180 top
CV208  1U_0402_6.3V6K  [C_0402]  216.34 115.61 270 top
CV209  1U_0402_6.3V6K  [C_0402]  223.13 115.53 270 top
CV210  1U_0402_6.3V6K  [C_0402]  217.23 115.58 270 top
CV211  1U_0402_6.3V6K  [C_0402]  222.23 115.53 270 top
